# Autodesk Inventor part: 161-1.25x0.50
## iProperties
Created: 2007-06
Part Number: 161-1.25x0.50
Document SubType Name: Modeling
Designer: btaylor
Density: 1 g/cm^3
Author: btaylor
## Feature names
1. Extrusion1
2. Extrusion2
3. Extrusion3
4. Extrusion4
5. Extrusion5
6. Fillet1
7. Fillet2
8. Fillet3
9. Extrusion6
10. Extrusion7
11. Extrusion8
12. Extrusion9
13. Extrusion10
14. Fillet4
15. Fillet5
16. Fillet6
17. Fillet7
18. Chamfer1
19. Chamfer2
20. Chamfer3
21. Fillet8
22. Fillet9
23. Fillet10
24. Fillet11
